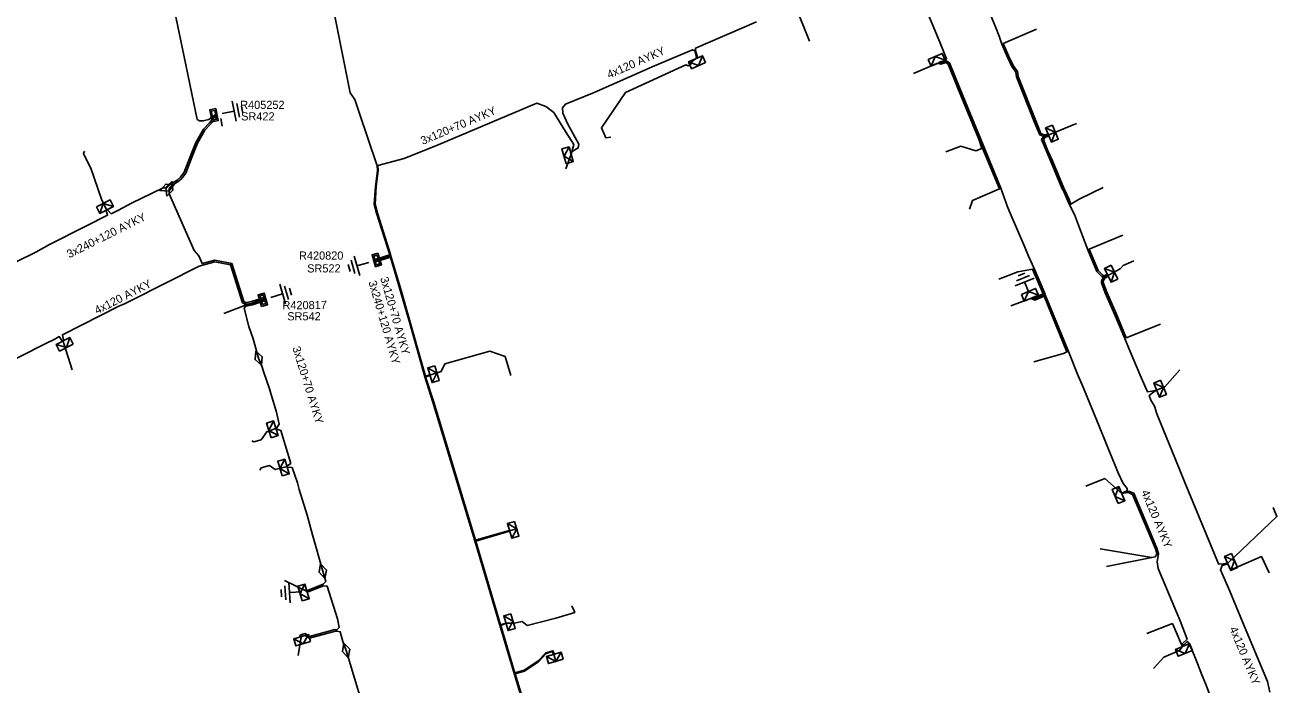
# Model space of a CAD drawing. Extents: x -540028 to -538776, y -1157064 to -1155670.
# Drawn here: x -539732.2 to -539579, y -1155979.1 to -1155898.3 of the extents above; entities that cross this region are included whole.
import ezdxf

# ---------------------------------------------------------------- set-up
doc = ezdxf.new("R2010")
doc.units = 0
for name, color, linetype in [('Vrstva 15', 7, 'Continuous'), ('Vrstva 19', 7, 'Continuous'), ('Vrstva 2', 7, 'Continuous'), ('Vrstva 28', 7, 'Continuous'), ('Vrstva 29', 7, 'Continuous'), ('Vrstva 30', 7, 'Continuous'), ('Vrstva 31', 7, 'Continuous'), ('Vrstva 5', 7, 'Continuous'), ('Vrstva 52', 7, 'Continuous'), ('Vrstva 59', 7, 'Continuous'), ('Vrstva 6', 7, 'Continuous')]:
    doc.layers.add(name, color=color, linetype=linetype)

# ---------------------------------------------------------------- blocks, each defined once
blk = doc.blocks.new('17')
at = {"layer": 'Vrstva 2'}
blk.add_lwpolyline([(-1.875, 0), (0, 0.9375), (1.875, 0), (0, -0.9375)], close=True, dxfattribs=at)
blk = doc.blocks.new('132')
at = {"layer": 'Vrstva 2'}
for points in [[(-1.5, 1.5), (1.5, 1.5), (1.5, 0), (-1.5, 0)], [(-1.1, 1.2), (1.1, 1.2), (1.1, 0.3), (-1.1, 0.3)]]:
    blk.add_lwpolyline(points, close=True, dxfattribs=at)
blk = doc.blocks.new('23')
at = {"layer": 'Vrstva 2'}
blk.add_lwpolyline([(1.875, -1.8), (-1.875, -1.8), (-1.875, 0), (1.875, 0)], close=True, dxfattribs=at)
blk.add_lwpolyline([(1.875, 0), (0, -1.8), (-1.875, 0)], dxfattribs=at)
blk = doc.blocks.new('11')
at = {"layer": 'Vrstva 2'}
for p, q in [((0, -4.3), (0, -1.3)), ((-2.5, -4.3), (2.5, -4.3)), ((-1.7, -5.3), (1.7, -5.3)), ((-0.9, -6.3), (0.9, -6.3))]:
    blk.add_line(p, q, dxfattribs=at)

msp = doc.modelspace()

# ---------------------------------------------------------------- linework, layer by layer
at = {"layer": 'Vrstva 5'}
for points in [[(-539696.27, -1155887.17), (-539692.42, -1155906.62), (-539691.84, -1155907.41), (-539691.34, -1155908.9), (-539689.11, -1155915.53), (-539689.08, -1155916.12), (-539689.32, -1155918.07), (-539689.46, -1155920.25), (-539689.17, -1155921.35), (-539687.57, -1155926.43), (-539689.53, -1155927.03)], [(-539617.94, -1155887.72), (-539613.46, -1155898.55), (-539612.98, -1155899.67), (-539612.67, -1155900.64), (-539611.98, -1155902.25), (-539611.46, -1155903.38), (-539610.94, -1155904.07), (-539610.89, -1155904.64), (-539608.63, -1155910.33), (-539608.03, -1155911.75), (-539607.61, -1155911.91), (-539607.05, -1155911.75), (-539606.96, -1155911.78), (-539607.03, -1155911.84), (-539607.61, -1155912.02), (-539607.81, -1155912.33), (-539607.22, -1155913.77), (-539606.67, -1155915.03), (-539605.27, -1155918.34), (-539605.14, -1155918.62), (-539604.62, -1155919.73), (-539604.39, -1155920.32), (-539603.79, -1155921.49), (-539602.81, -1155924.11), (-539602.16, -1155925.81), (-539601.05, -1155928.47), (-539600.42, -1155929.08), (-539600.27, -1155929.17), (-539599.78, -1155928.93), (-539599.71, -1155928.95)], [(-539620.47, -1155902.98), (-539620.21, -1155902.81), (-539619.6, -1155902.64), (-539619.44, -1155902.46), (-539619.6, -1155902.04), (-539620.25, -1155900.41), (-539621.2, -1155898.17), (-539624.42, -1155890.52), (-539624.79, -1155890.17), (-539625.2, -1155890.15), (-539628.31, -1155891.47), (-539628.46, -1155891.33), (-539628.76, -1155890.77)], [(-539713.86, -1155896.75), (-539713.19, -1155900.03), (-539711.12, -1155909.86), (-539710.85, -1155910.05), (-539710.38, -1155910.05), (-539709.72, -1155909.87), (-539708.73, -1155909.16)], [(-539642.69, -1155897.93), (-539650.15, -1155901.16), (-539650.14, -1155901.44), (-539649.91, -1155902.31), (-539650.14, -1155902.46), (-539650.04, -1155902.27), (-539650.25, -1155901.49), (-539650.53, -1155901.34), (-539655.45, -1155903.44), (-539656.57, -1155903.93), (-539662.54, -1155906.56), (-539666.07, -1155908.01), (-539666.42, -1155908.44), (-539666.37, -1155909.1), (-539665.78, -1155910.44), (-539664.44, -1155912.91), (-539664.5, -1155913.36), (-539665.46, -1155913.92), (-539665.37, -1155914.13)], [(-539620.47, -1155902.98), (-539620.18, -1155902.9), (-539619.49, -1155902.71), (-539619.08, -1155902.96), (-539617.87, -1155905.98), (-539616.85, -1155908.43), (-539615.3, -1155912.21), (-539614.84, -1155913.31), (-539612.79, -1155918.28), (-539611.99, -1155920.54), (-539611.65, -1155921.34), (-539609.86, -1155925.48), (-539609.42, -1155926.59), (-539608.72, -1155928.09), (-539607.39, -1155931.23), (-539608.71, -1155931.79), (-539608.95, -1155931.72), (-539609.06, -1155931.74), (-539608.97, -1155931.78), (-539608.67, -1155931.88), (-539607.35, -1155931.32), (-539604.52, -1155938.24), (-539603.35, -1155941.23), (-539602.83, -1155942.33), (-539601.72, -1155945.12), (-539600.77, -1155947.4), (-539599.89, -1155949.53), (-539598.43, -1155953.1), (-539597.81, -1155954.41), (-539597.32, -1155955), (-539597.33, -1155955.3), (-539597.89, -1155955.54), (-539597.98, -1155955.65), (-539597.12, -1155955.33), (-539596.52, -1155955.59), (-539593.69, -1155962.34), (-539593.49, -1155962.99), (-539593.67, -1155963.99), (-539593.55, -1155964.82), (-539591.29, -1155970.15), (-539590.87, -1155971.2), (-539590, -1155973.46), (-539590.56, -1155974), (-539590.57, -1155974.36), (-539590.38, -1155974.1), (-539589.99, -1155973.73), (-539589.79, -1155973.91), (-539589.62, -1155974.31), (-539589.4, -1155974.83), (-539589.13, -1155975.42), (-539588.73, -1155976.45), (-539588.18, -1155977.83), (-539587.77, -1155978.89), (-539586.81, -1155981.38)], [(-539714.8, -1155918.21), (-539714.34, -1155917.76), (-539713.59, -1155917.31), (-539713.17, -1155916.95), (-539712.71, -1155916.33), (-539711.94, -1155914.32), (-539711.29, -1155912.68), (-539710.35, -1155911.06), (-539709.64, -1155910.29), (-539708.71, -1155909.28)], [(-539689.51, -1155927.13), (-539687.44, -1155926.5), (-539689.07, -1155921.33), (-539689.36, -1155920.24), (-539689.22, -1155918.08), (-539688.98, -1155916.12), (-539689.01, -1155915.51), (-539685.81, -1155914.65), (-539681.64, -1155912.97), (-539669.57, -1155907.88), (-539668.48, -1155908.27), (-539667.49, -1155909.02), (-539666.07, -1155911.35), (-539665.06, -1155912.95), (-539665.37, -1155914.13)], [(-539714.54, -1155918.36), (-539714.24, -1155917.94), (-539713.45, -1155917.47), (-539713.03, -1155917.09), (-539712.53, -1155916.43), (-539711.76, -1155914.4), (-539711.11, -1155912.76), (-539710.19, -1155911.18), (-539709.5, -1155910.43), (-539708.66, -1155909.53)], [(-539714.8, -1155918.21), (-539715.37, -1155918.28), (-539719.18, -1155920.13), (-539720.76, -1155920.97), (-539721.65, -1155921.4), (-539722.08, -1155920.96), (-539722.21, -1155920.94), (-539722.26, -1155921.05), (-539722.1, -1155921.58), (-539724.74, -1155922.93), (-539729.19, -1155925.15), (-539730.86, -1155926.09), (-539740.2, -1155930.66)], [(-539702.83, -1155931.64), (-539702.99, -1155931.65), (-539703.94, -1155931.96), (-539704.48, -1155932.15), (-539705.07, -1155932.28), (-539705.15, -1155932.3), (-539705.42, -1155932.15), (-539706.88, -1155927.5), (-539708.98, -1155927.1), (-539710.53, -1155927.5), (-539710.91, -1155926.57), (-539711.49, -1155925.92), (-539714.22, -1155919.7), (-539714.54, -1155918.96), (-539714.54, -1155918.36)], [(-539702.77, -1155931.83), (-539702.95, -1155931.85), (-539703.88, -1155932.15), (-539704.42, -1155932.34), (-539705.03, -1155932.48), (-539705.19, -1155932.51), (-539705.58, -1155932.29), (-539707.04, -1155927.67), (-539708.98, -1155927.3), (-539710.89, -1155927.8), (-539719.19, -1155932.01), (-539720.09, -1155932.47), (-539720.64, -1155932.68), (-539727.62, -1155936.2), (-539727.48, -1155936.84), (-539727.55, -1155936.97), (-539727.69, -1155936.92), (-539728, -1155936.44), (-539728.65, -1155936.79), (-539729.55, -1155937.24), (-539736.14, -1155940.56)], [(-539689.48, -1155927.22), (-539687.42, -1155926.6), (-539686.25, -1155930.53), (-539685.14, -1155934.38), (-539684.17, -1155937.85), (-539683.21, -1155941.27), (-539682.78, -1155941.16), (-539682.66, -1155941.16)], [(-539669.36, -1155987.52), (-539672.43, -1155977.35), (-539674.01, -1155972.04), (-539677.15, -1155961.43), (-539682.28, -1155944.47), (-539683.29, -1155941.34), (-539684.27, -1155937.87), (-539685.24, -1155934.4), (-539687.48, -1155926.72), (-539689.45, -1155927.32)], [(-539599.71, -1155928.95), (-539599.74, -1155929.02), (-539600.3, -1155929.29), (-539600.49, -1155929.63), (-539600.47, -1155929.85), (-539600.02, -1155931.09), (-539598.87, -1155933.68), (-539597.63, -1155936.66), (-539597.08, -1155937.96), (-539595.61, -1155941.42), (-539594.83, -1155943.2), (-539594.31, -1155943.12), (-539593.73, -1155942.99), (-539594.23, -1155943.3), (-539594.63, -1155943.65), (-539594.44, -1155944.2), (-539593.99, -1155944.96), (-539593.71, -1155945.9), (-539591.44, -1155951.46), (-539590.27, -1155954.3), (-539586.17, -1155964.25), (-539585.74, -1155964.28), (-539585.16, -1155964.14), (-539585.04, -1155964.18), (-539585.11, -1155964.27), (-539585.72, -1155964.44), (-539585.9, -1155964.96), (-539584.78, -1155967.59), (-539583.21, -1155971.32), (-539580.16, -1155978.64), (-539579.89, -1155979.92)], [(-539689.74, -1155985.4), (-539692.91, -1155974.83), (-539693.29, -1155973.73), (-539693.63, -1155972.55), (-539694.02, -1155972.48), (-539694.22, -1155972.46), (-539697.4, -1155973.33), (-539697.94, -1155972.99), (-539698.27, -1155973.08), (-539698.41, -1155973.15), (-539698.5, -1155973.11), (-539698.57, -1155973), (-539698.34, -1155972.89), (-539697.9, -1155972.78), (-539697.37, -1155973.12), (-539694.28, -1155972.27), (-539694.06, -1155972.3), (-539693.76, -1155972.02), (-539693.97, -1155970.97), (-539695.22, -1155966.97), (-539695.67, -1155966.91), (-539697.56, -1155967.67), (-539697.69, -1155967.62), (-539697.64, -1155967.49), (-539695.72, -1155966.74), (-539695.4, -1155966.38), (-539695.77, -1155965.14), (-539697.03, -1155960.67), (-539697.69, -1155958.3), (-539698.64, -1155955.16), (-539698.84, -1155954.31), (-539699.51, -1155952.46), (-539700.03, -1155952.42), (-539700.14, -1155952.33), (-539700.07, -1155952.26), (-539699.68, -1155951.96), (-539700.88, -1155947.92), (-539701.4, -1155947.77), (-539701.51, -1155947.65), (-539701.44, -1155947.62), (-539701.11, -1155947.14), (-539701.43, -1155945.7), (-539702.12, -1155943.38), (-539702.3, -1155942.83), (-539702.97, -1155940.81), (-539703.22, -1155940.04), (-539703.61, -1155939.08), (-539704.29, -1155936.72), (-539704.8, -1155935.21), (-539705.37, -1155932.96), (-539705.19, -1155932.71), (-539704.36, -1155932.53), (-539702.91, -1155932.04), (-539702.72, -1155932.03)], [(-539682.66, -1155941.16), (-539682.76, -1155941.24), (-539683.18, -1155941.36), (-539682.18, -1155944.44), (-539677.07, -1155961.36), (-539672.96, -1155960.17), (-539672.9, -1155960.2), (-539672.93, -1155960.25), (-539677.04, -1155961.45), (-539674, -1155971.71), (-539673.34, -1155971.5)], [(-539673.34, -1155971.5), (-539673.98, -1155971.8), (-539672.33, -1155977.32), (-539672.26, -1155977.57), (-539671.13, -1155977.26), (-539669.43, -1155976.16), (-539668.48, -1155975.14), (-539667.61, -1155974.86), (-539667.45, -1155975.25), (-539667.49, -1155975.31), (-539667.54, -1155975.28), (-539667.68, -1155974.98), (-539668.42, -1155975.22), (-539669.37, -1155976.24), (-539671.09, -1155977.36), (-539672.23, -1155977.68), (-539669.26, -1155987.5)]]:
    msp.add_lwpolyline(points, dxfattribs=at)
at = {"layer": 'Vrstva 52'}
for points in [[(-539628.84, -1155890.81), (-539628.52, -1155891.46), (-539628.6, -1155891.74), (-539629.14, -1155891.98), (-539630.21, -1155892.46), (-539637.82, -1155895.71), (-539637.97, -1155895.92), (-539636.22, -1155900.28)], [(-539606.96, -1155911.78), (-539607.06, -1155911.65), (-539607.48, -1155911.75), (-539607.88, -1155911.59), (-539608.45, -1155910.25), (-539610.69, -1155904.6), (-539610.74, -1155903.99), (-539611.28, -1155903.28), (-539611.8, -1155902.17), (-539612.49, -1155900.57), (-539608.44, -1155898.84)], [(-539650.14, -1155902.46), (-539650.48, -1155902.7), (-539650.75, -1155903.14), (-539651.07, -1155903.29), (-539651.33, -1155903.2), (-539658.71, -1155906.56), (-539661.67, -1155910.89), (-539661.11, -1155912.11), (-539660.5, -1155912.05)], [(-539620.47, -1155902.98), (-539620.62, -1155903.04), (-539623.5, -1155904.26)], [(-539620.47, -1155902.98), (-539620.36, -1155902.99), (-539620.16, -1155903), (-539619.5, -1155902.82), (-539619.16, -1155903.03), (-539617.96, -1155906.02), (-539616.94, -1155908.47), (-539615.39, -1155912.25), (-539615.02, -1155913.39), (-539612.97, -1155918.36), (-539616.28, -1155919.77), (-539616.62, -1155920.83)], [(-539620.47, -1155902.98), (-539620.39, -1155903.04), (-539620.13, -1155903.09), (-539619.52, -1155902.92), (-539619.24, -1155903.1), (-539618.05, -1155906.06), (-539617.03, -1155908.51), (-539615.48, -1155912.29), (-539615.14, -1155913.43), (-539615.84, -1155913.69), (-539617.68, -1155913.14), (-539619.51, -1155913.85)], [(-539606.96, -1155911.78), (-539606.78, -1155911.7), (-539603.55, -1155910.36)], [(-539606.96, -1155911.78), (-539606.97, -1155911.93), (-539607.39, -1155912.03), (-539607.59, -1155912.35), (-539607.04, -1155913.69), (-539606.49, -1155914.95), (-539605.09, -1155918.26), (-539604.96, -1155918.54), (-539604.44, -1155919.65), (-539604.21, -1155920.24), (-539603.21, -1155919.63), (-539600.27, -1155918.2)], [(-539722.21, -1155920.94), (-539722.49, -1155920.39), (-539722.84, -1155919.63), (-539724.16, -1155915.83), (-539724.89, -1155914.4), (-539725.03, -1155914.02), (-539724.91, -1155913.77)], [(-539599.71, -1155928.95), (-539599.82, -1155928.84), (-539600.15, -1155929.01), (-539600.3, -1155928.92), (-539600.89, -1155928.35), (-539601.98, -1155925.73), (-539597.85, -1155924.01)], [(-539599.71, -1155928.95), (-539599.53, -1155928.86), (-539598.2, -1155928.16), (-539597.83, -1155927.73), (-539596.54, -1155927.15)], [(-539609.06, -1155931.74), (-539608.97, -1155931.67), (-539608.75, -1155931.7), (-539607.61, -1155931.22), (-539608.9, -1155928.17), (-539610.72, -1155928.51), (-539613.02, -1155929.4)], [(-539599.71, -1155928.95), (-539599.69, -1155929.1), (-539600.07, -1155929.3), (-539600.29, -1155929.67), (-539600.27, -1155929.81), (-539599.84, -1155931.01), (-539598.69, -1155933.6), (-539597.45, -1155936.58), (-539593.24, -1155934.91)], [(-539702.77, -1155931.93), (-539702.93, -1155931.95), (-539703.85, -1155932.24), (-539704.39, -1155932.44), (-539705.21, -1155932.61), (-539707.88, -1155933.61)], [(-539609.06, -1155931.74), (-539611.59, -1155932.69)], [(-539609.06, -1155931.74), (-539609.09, -1155931.79), (-539608.63, -1155931.98), (-539607.5, -1155931.49), (-539604.7, -1155938.32), (-539605.11, -1155938.5), (-539608.77, -1155939.51)], [(-539727.55, -1155936.97), (-539727.43, -1155937.26), (-539726.41, -1155940.49)], [(-539682.66, -1155941.16), (-539681.27, -1155940.72), (-539680.82, -1155939.77), (-539675.31, -1155938.2), (-539673.46, -1155938.89), (-539672.74, -1155941.19)], [(-539593.73, -1155942.99), (-539592.71, -1155942.58), (-539590.91, -1155940.52)], [(-539701.51, -1155947.65), (-539701.83, -1155947.8), (-539702.61, -1155948.08), (-539703.31, -1155949.05), (-539704.2, -1155949.31), (-539704.43, -1155949.17)], [(-539700.14, -1155952.33), (-539701.58, -1155952.71), (-539702.3, -1155952.22), (-539703.29, -1155952.51), (-539703.45, -1155952.77)], [(-539597.98, -1155955.65), (-539600.08, -1155953.79), (-539602.39, -1155954.74)], [(-539597.98, -1155955.65), (-539597.32, -1155955.51), (-539597.08, -1155955.57), (-539596.68, -1155955.75), (-539593.87, -1155962.4), (-539593.69, -1155963.05), (-539593.89, -1155963.37), (-539594.33, -1155963.46)], [(-539585.04, -1155964.18), (-539579.01, -1155958.46), (-539579.46, -1155957.35)], [(-539585.04, -1155964.18), (-539584.64, -1155964.96), (-539580.9, -1155963.34), (-539579.96, -1155965.35)], [(-539673.34, -1155971.5), (-539672.34, -1155971.5), (-539671.36, -1155971.31), (-539670.76, -1155971.8), (-539667.24, -1155970.88), (-539664.94, -1155970.19), (-539665.03, -1155969.92), (-539665.3, -1155969.39)], [(-539590.57, -1155974.36), (-539590.8, -1155973.83), (-539591.78, -1155971.55)], [(-539590.57, -1155974.36), (-539590.94, -1155974.83), (-539592.84, -1155975.66), (-539594.11, -1155977.03)]]:
    msp.add_lwpolyline(points, dxfattribs=at)
at = {"layer": 'Vrstva 59'}
for points in [[(-539708.23, -1155909.74), (-539708.09, -1155910.68)], [(-539665.37, -1155914.13), (-539666.03, -1155915.92)], [(-539672.9, -1155960.2), (-539671.94, -1155959.92)], [(-539594.33, -1155963.46), (-539600.65, -1155962.42)], [(-539594.33, -1155963.46), (-539599.86, -1155964.58)], [(-539697.69, -1155967.62), (-539700.44, -1155966.27)], [(-539591.78, -1155971.55), (-539594.93, -1155972.78)], [(-539698.41, -1155973.15), (-539698.78, -1155975.44)], [(-539667.49, -1155975.31), (-539667.21, -1155976.27)]]:
    msp.add_lwpolyline(points, dxfattribs=at)

# ---------------------------------------------------------------- block references
at = {"layer": 'Vrstva 15'}
for p, xscale, yscale, rotation in [((-539708.71, -1155909.28), 0.5, 0.5, 101.22079167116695), ((-539689.52, -1155927.17), 0.5, 0.5000000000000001, -73.62214727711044), ((-539609.06, -1155931.74), 0.5, 0.5, -157.4079498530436), ((-539702.74, -1155931.83), 0.5, 0.5, 106.49590001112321), ((-539697.69, -1155967.62), 0.49999999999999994, 0.5000000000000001, -86.29148886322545)]:
    msp.add_blockref('11', p, dxfattribs=dict(at, xscale=xscale, yscale=yscale, rotation=rotation))
at = {"layer": 'Vrstva 19'}
for p, xscale, yscale, rotation in [((-539714.8, -1155918.21), 0.5, 0.5, -156.88021949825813), ((-539714.54, -1155918.36), 0.5, 0.5000000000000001, 70.40521106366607), ((-539703.61, -1155939.08), 0.5, 0.5, -67.89055163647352), ((-539695.77, -1155965.14), 0.5, 0.5, 105.74203994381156), ((-539692.91, -1155974.83), 0.49999999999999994, 0.5000000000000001, -73.30572897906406)]:
    msp.add_blockref('17', p, dxfattribs=dict(at, xscale=xscale, yscale=yscale, rotation=rotation))
at = {"layer": 'Vrstva 28', "yscale": 0.5}
for p, xscale, rotation in [((-539708.71, -1155909.28), 0.5, 101.22079163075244), ((-539689.52, -1155927.17), 0.5000000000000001, -73.05959718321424), ((-539702.74, -1155931.83), 0.5, 106.49590001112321)]:
    msp.add_blockref('132', p, dxfattribs=dict(at, xscale=xscale, rotation=rotation))
at = {"layer": 'Vrstva 31'}
for p, xscale, yscale, rotation in [((-539650.14, -1155902.46), 0.5, 0.5, 23.555305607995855), ((-539620.47, -1155902.98), 0.5, 0.5, -157.00026944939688), ((-539606.96, -1155911.77), 0.5, 0.5, 112.558280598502), ((-539665.37, -1155914.13), 0.5, 0.5, -73.83173613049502), ((-539722.21, -1155920.94), 0.49999999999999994, 0.5000000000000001, -152.71746656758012), ((-539599.71, -1155928.95), 0.5, 0.5, 116.01149168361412), ((-539609.06, -1155931.74), 0.5, 0.5, -157.4079498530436), ((-539727.55, -1155936.97), 0.5, 0.5, 27.184447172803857), ((-539682.66, -1155941.16), 0.5, 0.5, 106.19838886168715), ((-539593.73, -1155942.99), 0.5, 0.5000000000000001, 112.62495560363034), ((-539701.51, -1155947.65), 0.49999999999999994, 0.5000000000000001, -73.14847227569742), ((-539700.14, -1155952.33), 0.49999999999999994, 0.5000000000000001, -73.3933416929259), ((-539597.98, -1155955.65), 0.49999999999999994, 0.5000000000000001, -67.46519722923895), ((-539672.9, -1155960.2), 0.5, 0.5, 106.31821674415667), ((-539585.04, -1155964.18), 0.5, 0.5, 113.54186386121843), ((-539697.69, -1155967.62), 0.5, 0.5000000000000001, -73.40972216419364), ((-539673.35, -1155971.5), 0.5, 0.5000000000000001, 106.7151027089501), ((-539698.41, -1155973.15), 0.49999999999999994, 0.5000000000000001, 16.749816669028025), ((-539667.5, -1155975.31), 0.5, 0.5, 16.452272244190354), ((-539590.57, -1155974.36), 0.5, 0.49999999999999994, 22.540047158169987)]:
    msp.add_blockref('23', p, dxfattribs=dict(at, xscale=xscale, yscale=yscale, rotation=rotation))

# ---------------------------------------------------------------- texts
at = {"layer": 'Vrstva 29'}
for s, rotation, p in [('R405252', 359.982, (-539705.87, -1155908.58)), ('R420817', 0.436, (-539700.69, -1155933.1))]:
    msp.add_text(s, height=1, rotation=rotation, dxfattribs=at).set_placement(p)
msp.add_text('R420820', height=1, dxfattribs=at).set_placement((-539698.67, -1155927.02))
at = {"layer": 'Vrstva 30'}
for s, rotation, p in [('SR422', 359.982, (-539705.75, -1155909.99)), ('SR522', 0.047, (-539697.67, -1155928.59)), ('SR542', 359.975, (-539700.11, -1155934.45))]:
    msp.add_text(s, height=1, rotation=rotation, dxfattribs=at).set_placement(p)
at = {"layer": 'Vrstva 6'}
for s, rotation, p in [('4x120 AYKY', 23.775, (-539660.72, -1155904.89)), ('3x120+70 AYKY', 22.865, (-539683.53, -1155912.99)), ('3x240+120 AYKY', 26.514, (-539726.78, -1155926.86)), ('3x120+70 AYKY', 286.083, (-539688.75, -1155929.29)), ('4x120 AYKY', 26.893, (-539723.38, -1155933.73)), ('3x240+120 AYKY', 286.271, (-539690.19, -1155929.75)), ('3x120+70 AYKY', 287.125, (-539699.5, -1155937.8)), ('4x120 AYKY', 292.824, (-539595.64, -1155955.44)), ('4x120 AYKY', 292.62, (-539584.85, -1155972.16))]:
    msp.add_text(s, height=1, rotation=rotation, dxfattribs=at).set_placement(p)

doc.saveas('drawing.dxf')
